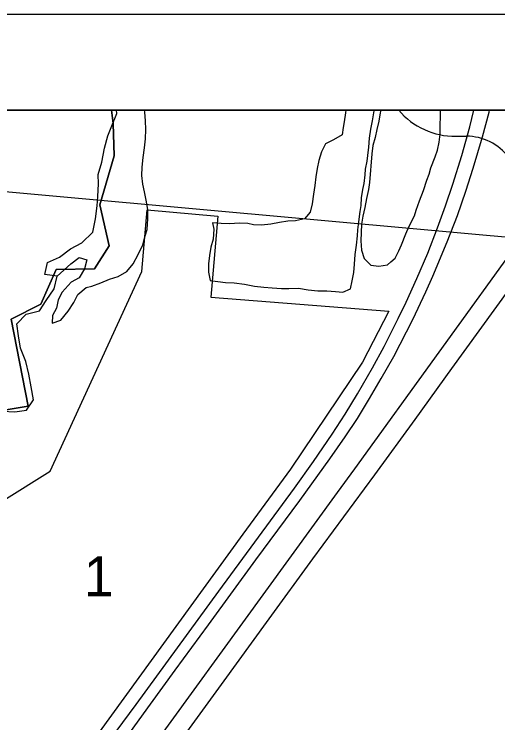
# Model space of a CAD drawing. Extents: x -209 to 4852, y 0 to 905.
# Drawn here: x 100.81 to 110.88, y 325.8 to 340.56 of the extents above; entities that cross this region are included whole.
import ezdxf

# ---------------------------------------------------------------- set-up
doc = ezdxf.new("R2010")
doc.units = 0
for name, color, linetype in [('Default', 7, 'Continuous'), ('GM_X_Airport_Location_Class_2', 7, 'Continuous'), ('GM_X_Corporation', 7, 'Continuous'), ('GM_X_County_Road', 7, 'Continuous'), ('GM_X_Interchange_Ramps', 7, 'Continuous'), ('GM_X_Major_River', 7, 'Continuous'), ('GM_X_Minor_Lake_Text', 7, 'Continuous'), ('GM_X_Minor_River', 7, 'Continuous'), ('GM_X_Township_Road_Text', 7, 'Continuous'), ('GM_X_US_Location', 7, 'Continuous'), ('GM_X_US_Route', 7, 'Continuous'), ('SH_Data', 7, 'Continuous')]:
    doc.layers.add(name, color=color, linetype=linetype)

msp = doc.modelspace()

# ---------------------------------------------------------------- linework, layer by layer
at = {"layer": 'Default'}
for points in [[(59.342, 338.559), (195.342, 338.559), (195.342, 202.559), (59.342, 202.559)], [(195.342, 202.559), (195.342, 338.559), (59.342, 338.559), (59.342, 202.559)]]:
    msp.add_lwpolyline(points, close=True, dxfattribs=at)
at = {"layer": 'GM_X_Airport_Location_Class_2'}
msp.add_lwpolyline([(100.635, 320.765), (100.879, 321.1), (101.138, 321.454), (101.471, 321.891), (101.832, 322.33), (102.235, 322.799), (102.722, 323.368), (103.032, 323.752), (103.379, 324.196), (103.741, 324.686), (105.127, 326.6), (106.118, 327.963), (107.027, 329.212), (108.315, 330.965), (109.157, 332.119), (109.921, 333.176), (111.116, 334.823)], dxfattribs=at)
at = {"layer": 'GM_X_Corporation'}
for points in [[(100.782, 322.675), (101.998, 324.325), (102.797, 325.434), (103.351, 326.183), (105.069, 328.544), (106.643, 330.687), (107.039, 331.24), (107.43, 331.813), (107.697, 332.226), (107.957, 332.653), (108.27, 333.195), (108.513, 333.639), (108.805, 334.222), (108.97, 334.563), (109.194, 335.055), (109.417, 335.584), (109.622, 336.11), (109.788, 336.568), (109.941, 337.017), (110.127, 337.617), (110.291, 338.214), (110.377, 338.559)], [(102.815, 325.037), (103.65, 326.187), (104.163, 326.895), (104.852, 327.843), (105.843, 329.191), (106.756, 330.429), (107.382, 331.295), (107.697, 331.759), (107.955, 332.141), (108.206, 332.551), (108.45, 332.969), (108.715, 333.432), (109.105, 334.2), (109.381, 334.773), (109.526, 335.105), (109.823, 335.82), (110.035, 336.368), (110.208, 336.871), (110.366, 337.35), (110.56, 338.006), (110.697, 338.519), (110.706, 338.559)]]:
    msp.add_lwpolyline(points, dxfattribs=at)
at = {"layer": 'GM_X_County_Road'}
msp.add_lwpolyline([(100.567, 332.292), (100.824, 332.275), (101.067, 332.311), (101.212, 332.53), (101.161, 332.796), (101.118, 333.061), (101.052, 333.327), (100.94, 333.601), (100.897, 333.86), (100.868, 334.11), (101.059, 334.313), (101.339, 334.379), (101.477, 334.598), (101.645, 334.84), (101.708, 335.105), (101.451, 335.137), (101.506, 335.387), (101.756, 335.499), (101.985, 335.671), (102.22, 335.799), (102.449, 336.017), (102.504, 336.297), (102.536, 336.57), (102.553, 336.759), (102.562, 337.025), (102.556, 337.222), (102.634, 337.479), (102.689, 337.767), (102.759, 338.024), (102.844, 338.236), (102.944, 338.493), (102.942, 338.559)], dxfattribs=at)
at = {"layer": 'GM_X_Interchange_Ramps'}
for p, q in [((113.39, 338.559), (108.813, 338.559)), ((110.003, 338.016), (110.223, 338.016))]:
    msp.add_line(p, q, dxfattribs=at)
for centre, radius, start, end in [((109.986, 339.554), 1.538, 220.3128, 270.6383), ((110.223, 336.918), 1.099, 36.8699, 90)]:
    msp.add_arc(centre, radius, start, end, dxfattribs=at)
at = {"layer": 'GM_X_Major_River'}
for points in [[(101.708, 335.105), (101.451, 335.137), (101.506, 335.387), (101.756, 335.499), (101.985, 335.671), (102.22, 335.799), (102.449, 336.017), (102.504, 336.297), (102.536, 336.57), (102.553, 336.759), (102.562, 337.025), (102.556, 337.222), (102.634, 337.479), (102.689, 337.767), (102.759, 338.024), (102.844, 338.236), (102.944, 338.493), (102.942, 338.559)], [(101.708, 335.105), (101.99, 335.36), (102.165, 335.488), (102.323, 335.441), (102.277, 335.252), (102.162, 335.071), (101.995, 334.974), (101.811, 334.77), (101.727, 334.612), (101.688, 334.437), (101.611, 334.286), (101.602, 334.12), (101.784, 334.186), (101.937, 334.375), (102.052, 334.556), (102.136, 334.722), (102.311, 334.865), (102.425, 334.894), (102.615, 334.961), (102.797, 335.043), (102.971, 335.095), (103.154, 335.2), (103.284, 335.358), (103.391, 335.554), (103.491, 335.758), (103.538, 335.94), (103.576, 336.076), (103.593, 336.296), (103.595, 336.493), (103.558, 336.683), (103.522, 336.858), (103.485, 337.017), (103.464, 337.2), (103.473, 337.374), (103.497, 337.571), (103.521, 337.776), (103.545, 337.965), (103.547, 338.155), (103.54, 338.337), (103.527, 338.519), (103.524, 338.559)], [(106.896, 336.345), (106.854, 336.293), (106.665, 336.257), (106.506, 336.25), (106.331, 336.221), (106.15, 336.185), (105.96, 336.164), (105.794, 336.173), (105.673, 336.196), (105.492, 336.205), (105.302, 336.192), (105.121, 336.201), (104.939, 336.21), (104.969, 336.08), (104.952, 335.876), (104.905, 335.709), (104.874, 335.535), (104.857, 335.361), (104.856, 335.186), (104.892, 335.012), (105.051, 334.988), (105.21, 334.971), (105.391, 334.962), (105.603, 334.938), (105.815, 334.891), (106.004, 334.874), (106.178, 334.857), (106.374, 334.848), (106.525, 334.847), (106.73, 334.853), (106.926, 334.821), (107.13, 334.797), (107.319, 334.795), (107.501, 334.786), (107.652, 334.77), (107.812, 334.837), (107.843, 335.004), (107.882, 335.178), (107.891, 335.352), (107.908, 335.557), (107.932, 335.746), (107.956, 335.943), (107.964, 336.064), (107.981, 336.231), (108.013, 336.451), (108.029, 336.572), (108.038, 336.731), (108.069, 336.906), (108.093, 337.034), (108.117, 337.216), (108.125, 337.33), (108.157, 337.496), (108.173, 337.618), (108.189, 337.792), (108.206, 337.974), (108.237, 338.163), (108.269, 338.337), (108.301, 338.549), (108.303, 338.559)], [(107.71, 338.559), (107.703, 338.501), (107.679, 338.319), (107.655, 338.198), (107.639, 338.047), (107.456, 337.942), (107.289, 337.86), (107.205, 337.694), (107.151, 337.512), (107.119, 337.345), (107.088, 337.171), (107.071, 336.989), (107.039, 336.807), (107.015, 336.61), (106.969, 336.436), (106.896, 336.345)], [(108.439, 338.559), (108.429, 338.503), (108.398, 338.329), (108.358, 338.155), (108.327, 337.988), (108.273, 337.822), (108.256, 337.647), (108.206, 337.056), (108.183, 336.905), (108.143, 336.723), (108.112, 336.534), (108.065, 336.352), (108.041, 336.185), (108.023, 335.836), (108.037, 335.647), (108.096, 335.472), (108.231, 335.334), (108.398, 335.31), (108.579, 335.339), (108.653, 335.402)], [(108.653, 335.402), (108.739, 335.474), (108.816, 335.633), (108.87, 335.754), (108.963, 335.981), (109.032, 336.147), (109.139, 336.359), (109.178, 336.48), (109.248, 336.669), (109.333, 336.888), (109.402, 337.1), (109.449, 337.228), (109.48, 337.357), (109.572, 337.591), (109.619, 337.728), (109.658, 337.894), (109.674, 338.061), (109.676, 338.243), (109.685, 338.432), (109.685, 338.559)]]:
    msp.add_lwpolyline(points, dxfattribs=at)
at = {"layer": 'GM_X_Minor_Lake_Text'}
for points in [[(100.044, 332.219), (101.101, 332.393), (100.745, 334.207), (101.365, 334.52), (101.683, 335.242), (102.479, 335.255), (102.785, 335.735), (102.59, 336.588), (102.892, 337.606), (102.868, 338.282), (102.839, 338.559), (59.342, 338.559)], [(195.342, 338.559), (102.839, 338.559), (102.868, 338.282), (102.892, 337.606), (102.59, 336.588), (102.785, 335.735), (102.479, 335.255), (101.683, 335.242), (101.365, 334.52), (100.745, 334.207), (101.101, 332.393), (100.044, 332.219)]]:
    msp.add_lwpolyline(points, dxfattribs=at)
at = {"layer": 'GM_X_Minor_River'}
for points in [[(114.819, 338.559), (94.444, 338.559), (94.333, 337.437), (114.544, 335.599)], [(94.333, 337.437), (114.544, 335.599), (112.672, 315.623), (92.468, 317.445)]]:
    msp.add_lwpolyline(points, close=True, dxfattribs=at)
at = {"layer": 'GM_X_US_Location'}
for points in [[(125.622, 338.559), (98.504, 338.559)], [(96.564, 327.92), (101.561, 331.041), (103.466, 335.199), (103.578, 336.482), (105.049, 336.353), (104.902, 334.663), (108.605, 334.375), (108.057, 333.314), (106.559, 331.084), (105.568, 329.731), (91.951, 310.954)]]:
    msp.add_lwpolyline(points, dxfattribs=at)
at = {"layer": 'GM_X_US_Route'}
msp.add_lwpolyline([(78.655, 290.839), (80.362, 293.189), (81.429, 294.658), (81.54, 294.81), (83.329, 297.271), (86.164, 301.171), (87.313, 302.756), (87.726, 303.323), (87.969, 303.658), (88.207, 303.986), (91.74, 308.847), (94.398, 312.5), (100.465, 320.845), (100.676, 321.133), (101.601, 322.421), (102.107, 323.11), (107.543, 330.594), (107.902, 331.087), (111.413, 335.948), (112.494, 337.404), (112.873, 337.925), (113.316, 338.559)], dxfattribs=at)
at = {"layer": 'SH_Data'}
msp.add_line((57.342, 340.559), (197.342, 340.559), dxfattribs=at)

# ---------------------------------------------------------------- texts
at = {"layer": 'GM_X_Township_Road_Text'}
msp.add_text('1', height=0.837, rotation=0, dxfattribs=at).set_placement((102.26, 328.431))

doc.saveas('drawing.dxf')
